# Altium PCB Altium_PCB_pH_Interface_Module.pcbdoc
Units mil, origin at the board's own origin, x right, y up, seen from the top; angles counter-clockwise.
Board outline 5273.58 x 6024 mil, 2 copper layers (Top Layer, Bottom Layer); 51 components, 44 nets, 193 pads, 0 vias.
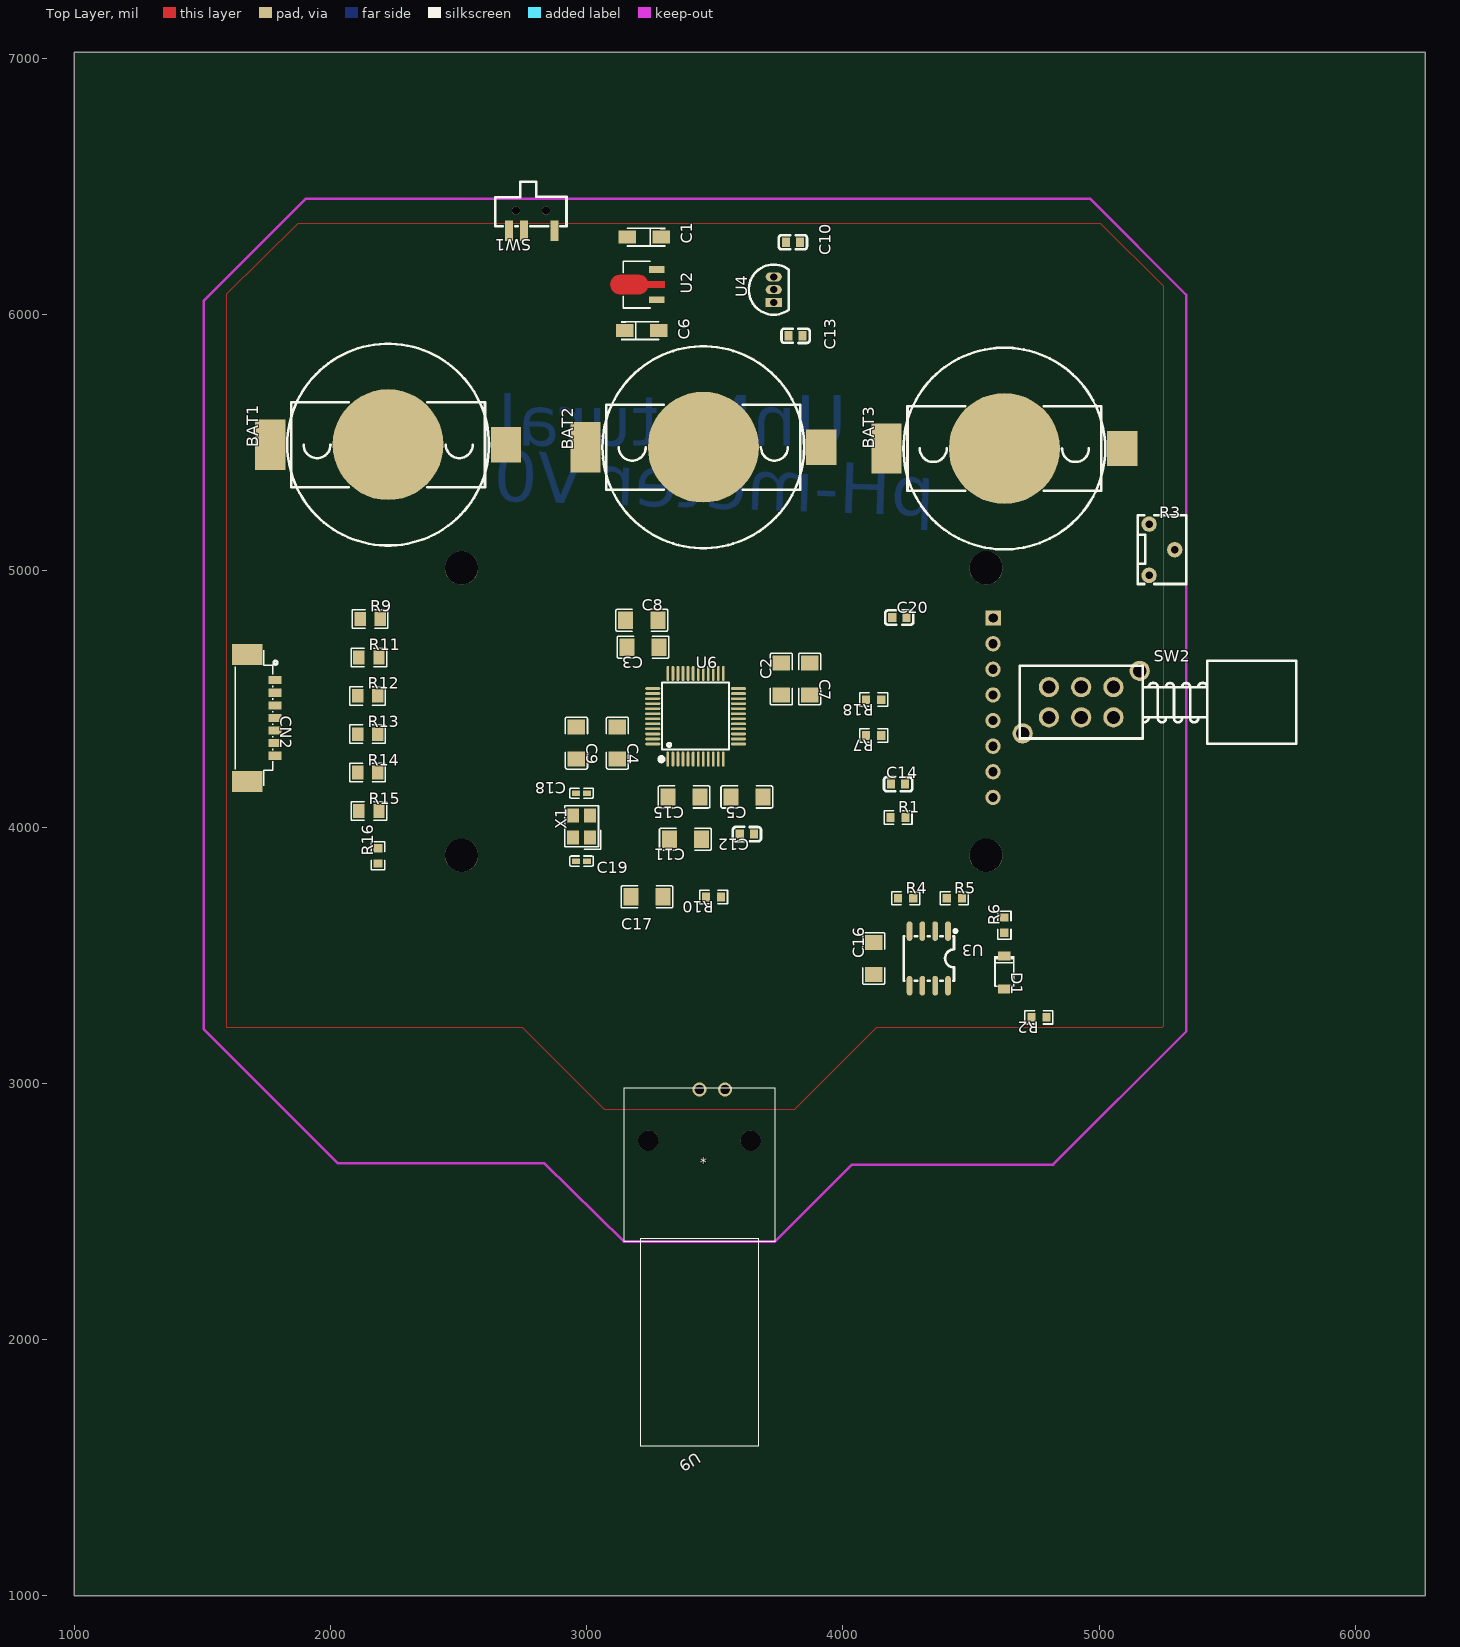
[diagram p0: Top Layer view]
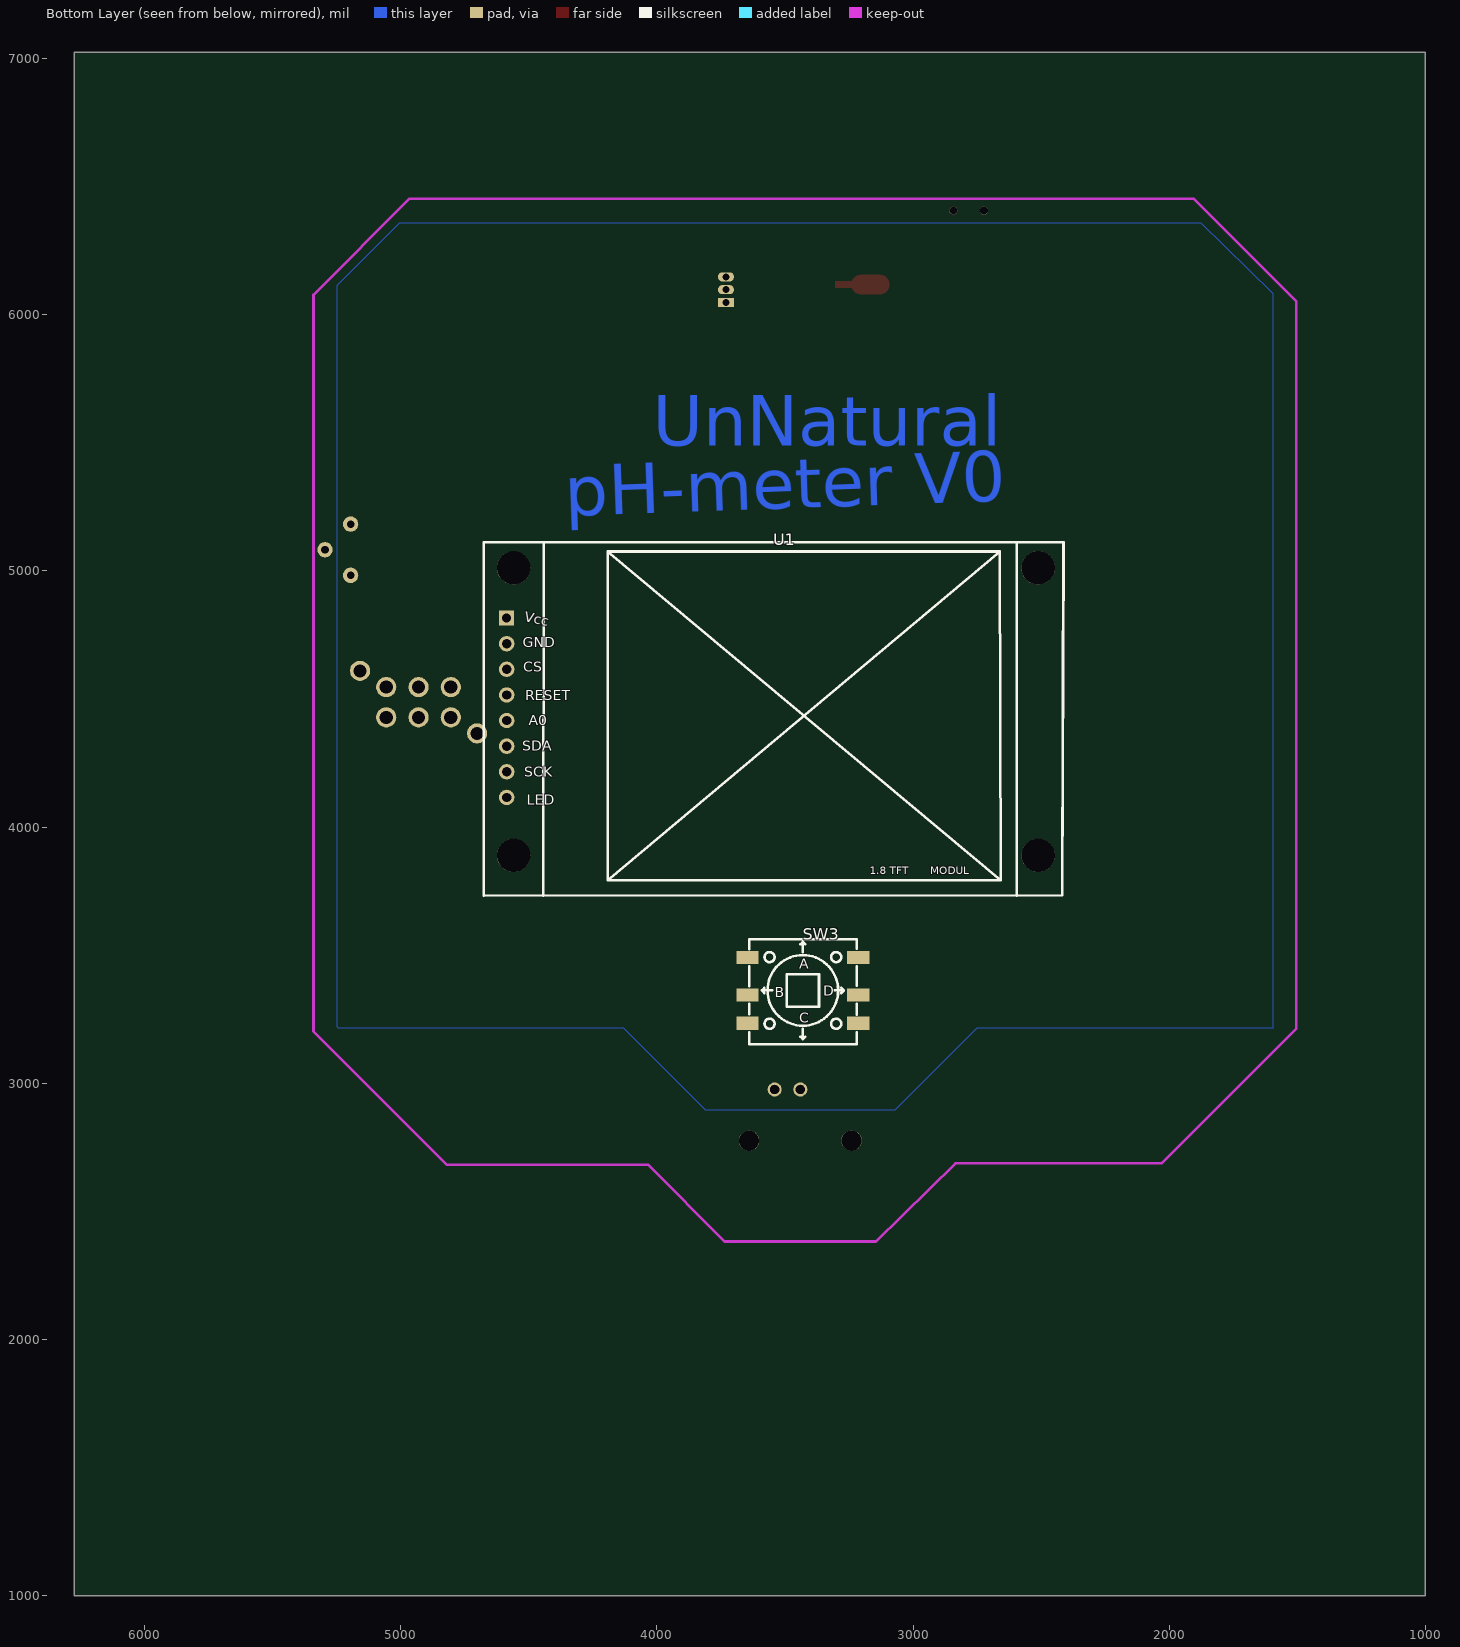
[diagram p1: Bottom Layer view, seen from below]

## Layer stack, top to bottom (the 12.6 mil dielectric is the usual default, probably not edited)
Top Layer: signal copper (thickness not stored)
Dielectric: dielectric 12.6, FR-4, Dk 4.8
Bottom Layer: signal copper (thickness not stored)

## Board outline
6273.58,1000 1000,1000 1000,7024 6273.58,7024

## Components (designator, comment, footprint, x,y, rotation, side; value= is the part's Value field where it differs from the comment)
BAT1 "MY-2032-10" BATTERY-SMD-MY-2032 2225,5492.46 r90 top
BAT2 "MY-2032-10" BATTERY-SMD-MY-2032 3455,5482.46 r90 top
BAT3 "MY-2032-10" BATTERY-SMD-MY-2032 4630,5477.46 r90 top
C1 "10uF" CAP-SMD_L3.2-W1.6-RD-C7171 3225,6302.46 r180 top
C2 "100nF" C1206 3760,4577.46 r90 top
C3 "100nF" C1206 3220,4702.46 r180 top
C4 "100nF" C1206 3120,4327.46 r270 top
C5 "100nF" C1206 3625,4117.46 r180 top
C6 "10uF" CAP-SMD_L3.2-W1.6-RD-C7171 3215,5937.46 r0 top
C7 "4.7uF" C1206 3870,4577.46 r270 top
C8 "4.7uF" C1206 3215,4807.46 r0 top
C9 "4.7uF" C1206 2960,4327.46 r270 top
C10 "330nF" C0603 3805,6282.46 r0 top
C11 "4.7uF" C1206 3385,3952.46 r180 top
C12 "10uF" C0603 3625,3972.46 r180 top
C13 "100nF" C0603 3815,5917.46 r180 top
C14 "100nF" C0603 4215,4167.46 r180 top
C15 "100nF" C1206 3380,4117.46 r180 top
C16 "100nF" C1206 4120,3487.46 r90 top
C17 "100nF" C1206 3235,3727.46 r0 top
C18 "13pF" C0402 2980,4132.46 r180 top
C19 "13pF" C0402 2980,3867.46 r0 top
C20 "100nF" C0603 4220,4817.46 r0 top
CN2 "53398-0771" CONN-SMD_7P-P1.25_53398-0771 1728.85,4425.89 r270 top
D1 "LMSZ5223BT1G" SOD-123_L2.7-W1.6-LS3.7-RD 4630,3432.46 r270 top
R1 "100Ω" R0603 4215,4037.46 r0 top
R2 "10kΩ" R0603 4765,3257.46 r180 top
R3 "20kΩ" RES-ADJ-TH_3362X 5245,5082.46 r0 top
R4 "10kΩ" R0603 4245,3722.46 r0 top
R5 "10kΩ" R0603 4435,3722.46 r0 top
R6 "240Ω" R0603 4630,3617.46 r90 top
R7 "10kΩ" R0603 4120,4357.46 r180 top
R9 "22Ω" R0805 2155,4812.46 r0 top
R10 "100kΩ" R0603 3495,3727.46 r180 top
R11 "22Ω" R0805 2150,4662.46 r0 top
R12 "22Ω" R0805 2145,4512.46 r0 top
R13 "22Ω" R0805 2145,4362.46 r0 top
R14 "22Ω" R0805 2145,4212.46 r0 top
R15 "22Ω" R0805 2150,4062.46 r0 top
R16 "10kΩ" R0603 2185,3887.46 r90 top
R18 "20kΩ" R0603 4120,4497.46 r180 top
SW1 "SSSS810701" SW-SMD_SSSS810701 2785,6327.46 r180 top
SW2 "PS22F02L-2B1-21" SW-TH_6P_PS22F02L-2B1-21 4930,4487.46 r0 top
SW3 "TM-2027" SW-SMD_6P-P2.80-L10.2-W10.2 3429.99,3362.47 r0 bottom
U1 "ST7735" "LCD ST7735" 4675,5112.46 r0 bottom
U2 "HT7533-1_C14289" SOT-89-3_L4.5-W2.5-P1.50-LS4.2-BR 3220,6117.46 r0 top
U3 "LMC662CMX/NOPB" SOIC-8_L5.0-W4.0-P1.27-LS6.1-BL 4335,3487.46 r180 top
U4 "LM78L05ATA" TO-92-3_L4.9-W3.7-P1.27-L 3730,6097.46 r90 top
U6 "STM32F030CCT6" LQFP-48_L7.0-W7.0-P0.50-LS9.0-BL 3425,4432.46 r0 top
U9 "NO" CONN_CONBN_LNX 3440,2682.46 r180 top
X1 "16MHz" CRYSTAL-SMD_4P-L3.2-W2.5-BL 2980,4002.46 r90 top

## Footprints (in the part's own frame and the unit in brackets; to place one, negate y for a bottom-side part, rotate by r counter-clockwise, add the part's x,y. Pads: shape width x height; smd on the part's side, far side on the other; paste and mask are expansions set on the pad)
BATTERY-SMD-MY-2032 [mm]
  rect 5x3 smd paste+0 mask+0.051: 1(0,11.684)
  rect 3.5x3 smd paste+0 mask+0.051: 1(0,-11.684)
  round 11 smd paste-100 mask+0.051: 2(0,0)
  silkscreen extent -10,-10 10,10
C0402 [mm]
  rect 0.79x0.54 smd paste-100 mask+0.051: 1(-0.545,0) 2(0.545,0)
  silkscreen extent -1.17,-0.5 1.17,0.5
C0603 [mm]
  rect 0.8x0.9 smd paste+0 mask+0.051: 1(-0.7,0) 2(0.7,0)
  silkscreen extent -1.41,-0.71 1.39,0.72
C1206 [mm]
  rect 1.485x1.728 smd paste-100 mask+0.051: 1(-1.593,0) 2(1.593,0)
  silkscreen extent -2.56,-1.09 2.56,1.09
CAP-SMD_L3.2-W1.6-RD-C7171 [mil]
  rect 69.19x51.02 smd paste+0 mask+2: 1(-66.39,0) 2(66.39,0)
  silkscreen extent -81,-37 66,37
CONN-SMD_7P-P1.25_53398-0771 [mm]
  rect 0.8x1.3 smd paste+0 mask+0.051: 1(-3.75,1.375) 2(-2.5,1.375) 3(-1.25,1.375) 4(0,1.375) 5(1.25,1.375) 6(2.5,1.375) 7(3.75,1.375)
  rect 2.1x3 smd paste+0 mask+0.051: 8(6.3,-1.375) 9(-6.3,-1.375)
  silkscreen extent -6.73,-2.54 6.73,1.61
CONN_CONBN_LNX [mil]
  round 55 hole 35 slot 35.2 at 0 deg paste+0 mask+2: 1(-100,-293.5) 2(0,-293.5)
  round 79 hole 79 unplated paste+0: ""(-200,-93.5) ""(200,-93.5)
  silkscreen extent -295,-299 295,1098
CRYSTAL-SMD_4P-L3.2-W2.5-BL [mm]
  rect 1.4x1.2 smd paste+0 mask+0.051: 1(-1.1,-0.85) 2(1.1,-0.85) 3(1.1,0.85) 4(-1.1,0.85)
  silkscreen extent -2.26,-1.91 2.03,1.68
"LCD ST7735" [mil]
  rect 60x60 hole 36 paste+0 mask+2: 1(-88.61,296.67)
  round 60 hole 36 paste+0 mask+2: 2(-89.05,396.74) 3(-89.05,496.74) 4(-89.05,596.74) 5(-89.05,696.74) 6(-89.05,796.74) 7(-89.05,896.74) 8(-89.05,996.74)
  round 129.92 hole 129.92 unplated paste+0: ""(-2163.55,1222.74) ""(-2163.45,100.64) ""(-116.25,100.74) ""(-116.25,1222.74)
  silkscreen extent -2262,0 0,1380
LQFP-48_L7.0-W7.0-P0.50-LS9.0-BL [mm]
  oval 0.27x1.5 smd paste+0 mask+0.05: 1(-2.75,-4.25) 2(-2.25,-4.25) 3(-1.75,-4.25) 4(-1.25,-4.25) 5(-0.75,-4.25) 6(-0.25,-4.25) 7(0.25,-4.25) 8(0.75,-4.25) 9(1.25,-4.25) 10(1.75,-4.25) 11(2.25,-4.25) 12(2.75,-4.25) 25(2.75,4.25) 26(2.25,4.25) 27(1.75,4.25) 28(1.25,4.25) 29(0.75,4.25) 30(0.25,4.25) 31(-0.25,4.25) 32(-0.75,4.25) 33(-1.25,4.25) 34(-1.75,4.25) 35(-2.25,4.25) 36(-2.75,4.25)
  oval 1.5x0.27 smd paste+0 mask+0.05: 13(4.25,-2.75) 14(4.25,-2.25) 15(4.25,-1.75) 16(4.25,-1.25) 17(4.25,-0.75) 18(4.25,-0.25) 19(4.25,0.25) 20(4.25,0.75) 21(4.25,1.25) 22(4.25,1.75) 23(4.25,2.25) 24(4.25,2.75) 37(-4.25,2.75) 38(-4.25,2.25) 39(-4.25,1.75) 40(-4.25,1.25) 41(-4.25,0.75) 42(-4.25,0.25) 43(-4.25,-0.25) 44(-4.25,-0.75) 45(-4.25,-1.25) 46(-4.25,-1.75) 47(-4.25,-2.25) 48(-4.25,-2.75)
  silkscreen extent -3.59,-4.46 3.3,3.34
R0603 [mil]
  rect 31.75x34.02 smd paste-3937.01 mask+2: 1(-29.65,0) 2(29.65,0)
  silkscreen extent -55,-26 55,26
R0805 [mil]
  rect 44.59x54.21 smd paste-3937.01 mask+2: 1(-39.37,0) 2(39.37,0)
  silkscreen extent -69,-36 69,36
RES-ADJ-TH_3362X [mil]
  round 60 hole 30 paste+0 mask+2: 1(-50,-100) 2(50,0) 3(-50,100)
  silkscreen extent -94,-134 94,134
SOD-123_L2.7-W1.6-LS3.7-RD [mm]
  rect 0.91x1.22 smd paste+0 mask+0.051: 1(-1.635,0) 2(1.635,0)
  silkscreen extent -1.6,-1 1.38,1
SOIC-8_L5.0-W4.0-P1.27-LS6.1-BL [mil]
  oval 22.38x76.78 smd paste+0 mask+2: 1(-75,-106.5) 2(-25,-106.5) 3(25,-106.5) 4(75,-106.5) 5(75,106.5) 6(25,106.5) 7(-25,106.5) 8(-75,106.5)
  silkscreen extent -110,-112 98,87
SOT-89-3_L4.5-W2.5-P1.50-LS4.2-BR [mm]
  rect 1.575x0.672 smd paste+0 mask+0.051: 1(1.356,-1.5) 3(1.356,1.5)
  Top Layer region: -2.283,0.95 -0.429,0.95 -0.384,0.949 -0.34,0.946 -0.296,0.94 -0.252,0.933 -0.208,0.924 -0.165,0.912 -0.123,0.899 -0.081,0.884 -0.04,0.866 0,0.847 0.04,0.826 0.078,0.803 0.115,0.779 0.151,0.752 0.185,0.724 0.219,0.695 0.251,0.664 0.281,0.631 0.31,0.597 0.337,0.562 0.362,0.525 0.386,0.488 0.408,0.449 0.428,0.409 0.447,0.33 2.144,0.33 2.144,-0.33 0.447,-0.33 0.428,-0.409 0.408,-0.449 0.386,-0.488 0.362,-0.526 0.337,-0.562 0.31,-0.597 0.281,-0.631 0.251,-0.664 0.219,-0.695 0.185,-0.725 0.151,-0.753 0.115,-0.779 0.078,-0.804 0.04,-0.827 0,-0.848 -0.04,-0.867 -0.081,-0.884 -0.123,-0.899 -0.165,-0.913 -0.208,-0.924 -0.252,-0.934 -0.296,-0.941 -0.34,-0.946 -0.384,-0.949 -0.429,-0.95 -2.283,-0.95 -2.328,-0.949 -2.372,-0.946 -2.416,-0.941 -2.46,-0.934 -2.504,-0.924 -2.547,-0.913 -2.589,-0.899 -2.631,-0.884 -2.672,-0.867 -2.713,-0.848 -2.752,-0.827 -2.79,-0.804 -2.827,-0.779 -2.863,-0.753 -2.898,-0.725 -2.931,-0.695 -2.963,-0.664 -2.993,-0.631 -3.022,-0.597 -3.049,-0.562 -3.075,-0.526 -3.098,-0.488 -3.12,-0.449 -3.141,-0.409 -3.159,-0.369 -3.175,-0.327 -3.189,-0.285 -3.202,-0.242 -3.212,-0.199 -3.22,-0.155 -3.227,-0.111 -3.231,-0.067 -3.233,-0.022 -3.233,0.022 -3.231,0.067 -3.227,0.111 -3.22,0.155 -3.212,0.199 -3.202,0.242 -3.189,0.285 -3.175,0.327 -3.159,0.369 -3.141,0.409 -3.12,0.449 -3.098,0.488 -3.075,0.525 -3.049,0.562 -3.022,0.597 -2.993,0.631 -2.963,0.664 -2.931,0.695 -2.898,0.724 -2.863,0.752 -2.827,0.779 -2.79,0.803 -2.752,0.826 -2.713,0.847 -2.672,0.866 -2.631,0.884 -2.589,0.899 -2.547,0.912 -2.504,0.924 -2.46,0.933 -2.416,0.94 -2.372,0.946 -2.328,0.949
  silkscreen extent -1.95,-2.33 0.7,2.33
SW-SMD_6P-P2.80-L10.2-W10.2 [mm]
  rect 2.2x1.3 smd paste+0 mask+0.051: 1(5.5,-3.25) 2(5.5,0.45) 3(5.5,3.25) 4(-5.5,3.25) 5(-5.5,0.45) 6(-5.5,-3.25)
  silkscreen extent -5.35,-5.08 5.33,5.33
SW-SMD_SSSS810701 [mm]
  rect 0.8x2 smd paste+0 mask+0.051: 1(-2.25,0) 2(0.75,0) 3(2.25,0)
  round 0.8 hole 0.8 unplated paste+0: ""(-1.45,-2) ""(1.552,-2.003)
  silkscreen extent -3.47,-4.86 3.59,-0.44
SW-TH_6P_PS22F02L-2B1-21 [mm]
  round 2 hole 1.3 paste+0 mask+0.051: 1(-3.2,-1.5) 2(0,-1.5) 3(3.2,-1.5) 4(-3.2,1.5) 5(0,1.5) 6(3.2,1.5) M(-5.8,-3.1) M(5.8,3.1)
  silkscreen extent -6.1,-4.1 21.3,4.1
TO-92-3_L4.9-W3.7-P1.27-L [mm]
  rect 0.9x1.6 hole 0.7 paste+0 mask+0.051: 1(-1.27,0)
  oval 0.9x1.6 hole 0.7 paste+0 mask+0.051: 2(0,0) 3(1.27,0)
  silkscreen extent -2.48,-1.5 2.48,2.48

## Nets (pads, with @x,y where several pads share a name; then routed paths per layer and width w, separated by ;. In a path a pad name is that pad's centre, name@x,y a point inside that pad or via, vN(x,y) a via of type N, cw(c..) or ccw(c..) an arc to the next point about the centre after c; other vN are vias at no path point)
3.3V: C1.1 C2.2 C3.2 C4.2 C5.2 C7.1 C8.1 C9.1 C11.1 C12.2 C14.2 C15.2 C20.2 R1.1 R9.2 R10.1 U1.1 U2.3 U6.1 U6.9 U6.24 U6.36 U6.48
+5V: C13.2 C16.2 R6.2 U3.4 U4.1
ADC1_IN8: R5.2 R7.2 U3.1
BAT1_2: BAT1.2 BAT2.1
BAT2_2: BAT2.2 BAT3.1
BLTX: R14.2 U6.38
BOOT0: R15.2 R16.2 U6.44
D1_1: D1.1 R3.1 R6.1
DOWN: SW3.3 U6.3
GND: BAT3.2 C1.2 C2.1 C3.1 C4.1 C5.1 C6.2 C7.2 C8.2 C9.2 C10.2 C11.2 C12.1 C13.1 C14.1 C15.1 C16.1 C17.1 C18.2 C19.1 C20.1 CN2.7 D1.2 R2.1 R4.1 R16.1 R18.2 SW2.5 SW3.4 U1.2 U2.1 U3.8 U4.2 U6.8 U6.23 U6.35 U6.47 X1.2 X1.4
LEFT: SW3.2 U6.10
NRST: C17.2 R10.2 R11.2 U6.7
OPAMP-CALIB: SW2.4 U6.25
OSC-IN: C18.1 U6.5 X1.3
OSC-OUT: C19.2 U6.6 X1.1
PH+: SW2.1 U3.3 U9.1
PH-: SW2.2 U3.6 U3.7 U9.2
R1_2: R1.2 U1.8
R2_2: R2.2 R3.2 R3.3 U3.5
R4_2: R4.2 R5.1 U3.2
R9_1: CN2.1 R9.1
R11_1: CN2.2 R11.1
R12_1: CN2.3 R12.1
R13_1: CN2.4 R13.1
R14_1: CN2.5 R14.1
R15_1: CN2.6 R15.1
RIGHT: SW3.5 U6.11
S$154: 
S$66725: 
S$66729: 
S$66742: 
SEL: SW3.6 U6.4
SPI1-MOSI: U1.6 U6.17
SPI1-SCK: U1.7 U6.15
ST7735-AD: U1.5 U6.19
ST7735-CS: U1.3 U6.21
ST7735-RESET: U1.4 U6.20
SW2_M: SW2.M
SWCLK: R12.2 U6.37
SWDIO: R13.2 U6.34
U2_2: C6.1 C10.1 SW1.1 U4.3
U6_18: R7.1 R18.1 U6.18
UP: SW3.1 U6.2
VBAT: BAT1.1 SW1.2
pads on no net: CN2.8 CN2.9 SW1. SW1.3 SW2.3 SW2.6 U1. U6.12 U6.13 U6.14 U6.16 U6.22 U6.26 U6.27 U6.28 U6.29 U6.30 U6.31 U6.32 U6.33 U6.39 U6.40 U6.41 U6.42 U6.43 U6.45 U6.46 U9.

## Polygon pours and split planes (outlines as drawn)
GND on Bottom Layer (solid): 4130,3217.46 3810,2897.46 3070,2897.46 2750,3217.46 1595,3217.46 1595,6082.46 1875,6357.46 5005,6357.46 5250,6112.46 5250,3222.46 5245,3217.46 4130,3217.46
3.3V on Top Layer (solid): 4130,3217.46 3810,2897.46 3070,2897.46 2750,3217.46 1595,3217.46 1595,6082.46 1875,6357.46 5005,6357.46 5250,6112.46 5250,3222.46 5245,3217.46 4130,3217.46

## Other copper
Bottom Layer:
  text "UnNatural" at 4015,5489.04 h196.85
  text "pH-meter V0" at 4356.56,5214.1 h196.85 r358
